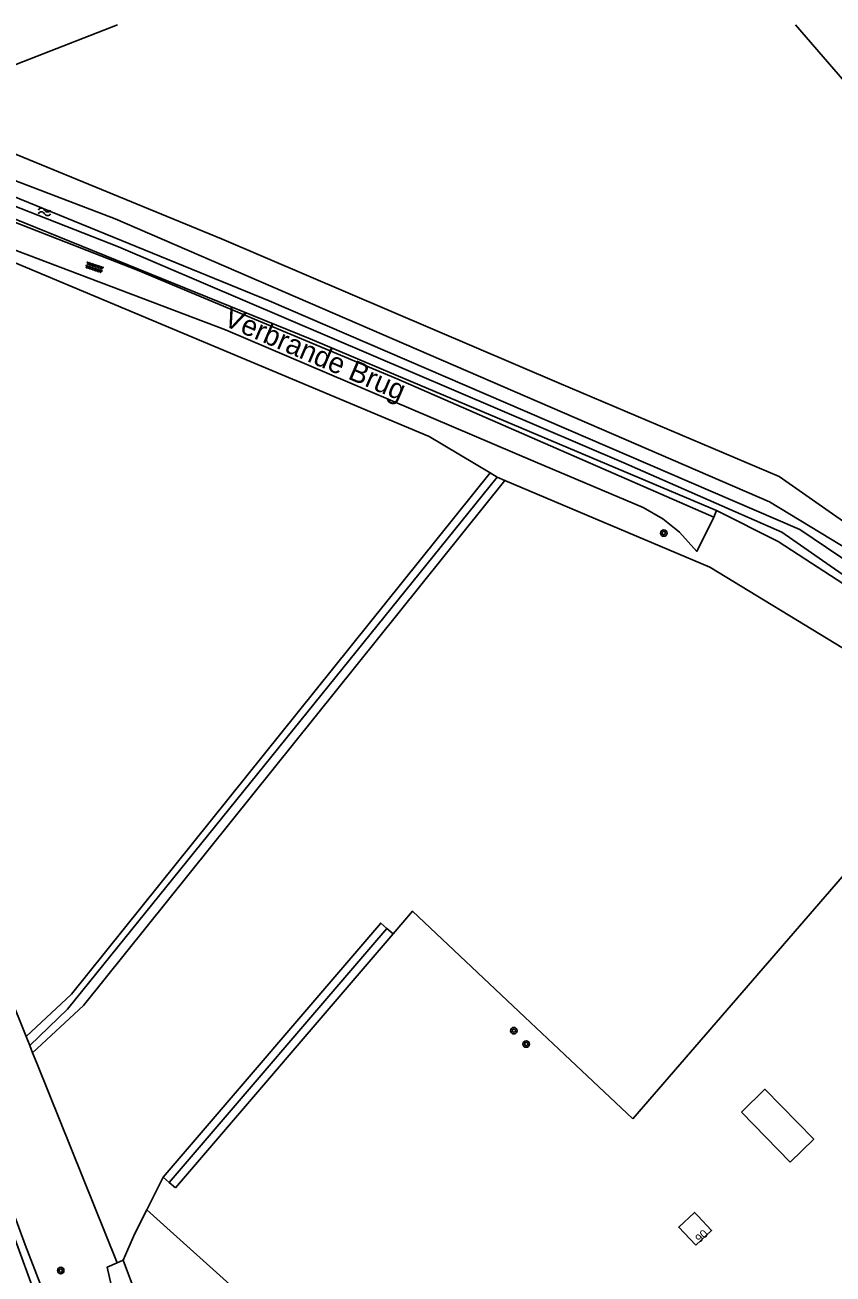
# Model space of a CAD drawing. Extents: x 135990 to 139000, y 393500 to 396000.
# Drawn here: x 136176.4 to 136274.9, y 395847.7 to 396000 of the extents above; entities that cross this region are included whole.
import ezdxf

# ---------------------------------------------------------------- set-up
doc = ezdxf.new("R2010")
doc.units = 0
for name, color, linetype in [('gg-anno-huisnummerreeks BGT', 7, 'Continuous'), ('gg-anno-openbare ruimte label', 7, 'Continuous'), ('gg-bbg-gedigitaliseerde bijgebouw', 7, 'Continuous'), ('gg-bbg-hoofdgebouw', 7, 'Continuous'), ('gg-knt-bovenkant onderkant talud', 7, 'Continuous'), ('gg-knt-bronhoudergrens', 7, 'Continuous'), ('gg-knt-onverhard', 7, 'Continuous'), ('gg-knt-verharding', 7, 'Continuous'), ('gg-kntw-bovenkant insteek waterloop', 7, 'Continuous'), ('gg-kntw-midden sloot', 7, 'Continuous'), ('gg-kntw-waterlijn', 7, 'Continuous'), ('gt-grn-groengrens', 7, 'Continuous'), ('gt-symb-boom', 7, 'Continuous'), ('gt-symb-overige verharding', 7, 'Continuous'), ('gt-symb-watersymbool', 7, 'Continuous')]:
    doc.layers.add(name, color=color, linetype=linetype)

# ---------------------------------------------------------------- blocks, each defined once
blk = doc.blocks.new('gt0-BOOM')
at = {"layer": 'gt-symb-boom'}
for radius in [0.4, 0.2]:
    blk.add_circle((0, 0), radius, dxfattribs=at)
blk = doc.blocks.new('gt0-WA')
at = {"layer": 'gt-symb-watersymbool'}
for centre, start, end in [((-0.32, 0.02), 28.0725, 151.9275), ((0.43, 0.42), 208.0725, 331.9275), ((-0.32, -0.43), 28.0725, 151.9275), ((0.43, -0.03), 208.0725, 331.9275)]:
    blk.add_arc(centre, 0.425, start, end, dxfattribs=at)
blk = doc.blocks.new('gt0-OVH')
at = {"layer": 'gt-symb-overige verharding'}
for points in [[(-0.97, 0.3), (-0.97, 0.31), (-0.96, 0.32), (-0.97, 0.33), (-0.97, 0.34), (-0.98, 0.35), (-0.99, 0.35), (-1, 0.36), (-1.01, 0.35), (-1.02, 0.35), (-1.03, 0.34), (-1.03, 0.33), (-1.04, 0.32), (-1.03, 0.31), (-1.03, 0.3), (-1.02, 0.29), (-1.01, 0.29), (-1, 0.28), (-0.99, 0.29), (-0.98, 0.29)], [(-0.87, 0.11), (-0.87, 0.12), (-0.86, 0.13), (-0.87, 0.14), (-0.87, 0.15), (-0.88, 0.16), (-0.89, 0.16), (-0.9, 0.16), (-0.91, 0.16), (-0.92, 0.16), (-0.93, 0.15), (-0.93, 0.14), (-0.94, 0.13), (-0.93, 0.12), (-0.93, 0.11), (-0.92, 0.1), (-0.91, 0.09), (-0.9, 0.09), (-0.89, 0.09), (-0.88, 0.1)], [(-0.77, 0.3), (-0.77, 0.31), (-0.76, 0.32), (-0.77, 0.33), (-0.77, 0.34), (-0.78, 0.35), (-0.79, 0.35), (-0.8, 0.36), (-0.81, 0.35), (-0.82, 0.35), (-0.83, 0.34), (-0.83, 0.33), (-0.84, 0.32), (-0.83, 0.31), (-0.83, 0.3), (-0.82, 0.29), (-0.81, 0.29), (-0.8, 0.28), (-0.79, 0.29), (-0.78, 0.29)], [(-0.67, 0.11), (-0.67, 0.12), (-0.66, 0.13), (-0.67, 0.14), (-0.67, 0.15), (-0.68, 0.16), (-0.69, 0.16), (-0.7, 0.16), (-0.71, 0.16), (-0.72, 0.16), (-0.73, 0.15), (-0.73, 0.14), (-0.74, 0.13), (-0.73, 0.12), (-0.73, 0.11), (-0.72, 0.1), (-0.71, 0.09), (-0.7, 0.09), (-0.69, 0.09), (-0.68, 0.1)], [(-0.57, 0.3), (-0.57, 0.31), (-0.56, 0.32), (-0.57, 0.33), (-0.57, 0.34), (-0.58, 0.35), (-0.59, 0.35), (-0.6, 0.36), (-0.61, 0.35), (-0.62, 0.35), (-0.63, 0.34), (-0.63, 0.33), (-0.64, 0.32), (-0.63, 0.31), (-0.63, 0.3), (-0.62, 0.29), (-0.61, 0.29), (-0.6, 0.28), (-0.59, 0.29), (-0.58, 0.29)], [(-0.47, 0.11), (-0.47, 0.12), (-0.46, 0.13), (-0.47, 0.14), (-0.47, 0.15), (-0.48, 0.16), (-0.49, 0.16), (-0.5, 0.16), (-0.51, 0.16), (-0.52, 0.16), (-0.53, 0.15), (-0.53, 0.14), (-0.54, 0.13), (-0.53, 0.12), (-0.53, 0.11), (-0.52, 0.1), (-0.51, 0.09), (-0.5, 0.09), (-0.49, 0.09), (-0.48, 0.1)], [(-0.37, 0.3), (-0.37, 0.31), (-0.36, 0.32), (-0.37, 0.33), (-0.37, 0.34), (-0.38, 0.35), (-0.39, 0.35), (-0.4, 0.36), (-0.41, 0.35), (-0.42, 0.35), (-0.43, 0.34), (-0.43, 0.33), (-0.44, 0.32), (-0.43, 0.31), (-0.43, 0.3), (-0.42, 0.29), (-0.41, 0.29), (-0.4, 0.28), (-0.39, 0.29), (-0.38, 0.29)], [(-0.27, 0.11), (-0.27, 0.12), (-0.26, 0.13), (-0.27, 0.14), (-0.27, 0.15), (-0.28, 0.16), (-0.29, 0.16), (-0.3, 0.16), (-0.31, 0.16), (-0.32, 0.16), (-0.33, 0.15), (-0.33, 0.14), (-0.34, 0.13), (-0.33, 0.12), (-0.33, 0.11), (-0.32, 0.1), (-0.31, 0.09), (-0.3, 0.09), (-0.29, 0.09), (-0.28, 0.1)], [(-0.17, 0.3), (-0.17, 0.31), (-0.16, 0.32), (-0.17, 0.33), (-0.17, 0.34), (-0.18, 0.35), (-0.19, 0.35), (-0.2, 0.36), (-0.21, 0.35), (-0.22, 0.35), (-0.23, 0.34), (-0.23, 0.33), (-0.24, 0.32), (-0.23, 0.31), (-0.23, 0.3), (-0.22, 0.29), (-0.21, 0.29), (-0.2, 0.28), (-0.19, 0.29), (-0.18, 0.29)], [(-0.07, 0.11), (-0.07, 0.12), (-0.06, 0.13), (-0.07, 0.14), (-0.07, 0.15), (-0.08, 0.16), (-0.09, 0.16), (-0.1, 0.16), (-0.11, 0.16), (-0.12, 0.16), (-0.13, 0.15), (-0.13, 0.14), (-0.14, 0.13), (-0.13, 0.12), (-0.13, 0.11), (-0.12, 0.1), (-0.11, 0.09), (-0.1, 0.09), (-0.09, 0.09), (-0.08, 0.1)], [(0.03, 0.3), (0.03, 0.31), (0.04, 0.32), (0.03, 0.33), (0.03, 0.34), (0.02, 0.35), (0.01, 0.35), (0, 0.36), (-0.01, 0.35), (-0.02, 0.35), (-0.03, 0.34), (-0.03, 0.33), (-0.04, 0.32), (-0.03, 0.31), (-0.03, 0.3), (-0.02, 0.29), (-0.01, 0.29), (0, 0.28), (0.01, 0.29), (0.02, 0.29)], [(0.13, 0.11), (0.13, 0.12), (0.14, 0.13), (0.13, 0.14), (0.13, 0.15), (0.12, 0.16), (0.11, 0.16), (0.1, 0.16), (0.09, 0.16), (0.08, 0.16), (0.07, 0.15), (0.07, 0.14), (0.06, 0.13), (0.07, 0.12), (0.07, 0.11), (0.08, 0.1), (0.09, 0.09), (0.1, 0.09), (0.11, 0.09), (0.12, 0.1)], [(0.23, 0.3), (0.23, 0.31), (0.24, 0.32), (0.23, 0.33), (0.23, 0.34), (0.22, 0.35), (0.21, 0.35), (0.2, 0.36), (0.19, 0.35), (0.18, 0.35), (0.17, 0.34), (0.17, 0.33), (0.16, 0.32), (0.17, 0.31), (0.17, 0.3), (0.18, 0.29), (0.19, 0.29), (0.2, 0.28), (0.21, 0.29), (0.22, 0.29)], [(0.33, 0.11), (0.33, 0.12), (0.34, 0.13), (0.33, 0.14), (0.33, 0.15), (0.32, 0.16), (0.31, 0.16), (0.3, 0.16), (0.29, 0.16), (0.28, 0.16), (0.27, 0.15), (0.27, 0.14), (0.26, 0.13), (0.27, 0.12), (0.27, 0.11), (0.28, 0.1), (0.29, 0.09), (0.3, 0.09), (0.31, 0.09), (0.32, 0.1)], [(0.43, 0.3), (0.43, 0.31), (0.44, 0.32), (0.43, 0.33), (0.43, 0.34), (0.42, 0.35), (0.41, 0.35), (0.4, 0.36), (0.39, 0.35), (0.38, 0.35), (0.37, 0.34), (0.37, 0.33), (0.36, 0.32), (0.37, 0.31), (0.37, 0.3), (0.38, 0.29), (0.39, 0.29), (0.4, 0.28), (0.41, 0.29), (0.42, 0.29)], [(0.53, 0.11), (0.53, 0.12), (0.54, 0.13), (0.53, 0.14), (0.53, 0.15), (0.52, 0.16), (0.51, 0.16), (0.5, 0.16), (0.49, 0.16), (0.48, 0.16), (0.47, 0.15), (0.47, 0.14), (0.46, 0.13), (0.47, 0.12), (0.47, 0.11), (0.48, 0.1), (0.49, 0.09), (0.5, 0.09), (0.51, 0.09), (0.52, 0.1)], [(0.63, 0.3), (0.63, 0.31), (0.64, 0.32), (0.63, 0.33), (0.63, 0.34), (0.62, 0.35), (0.61, 0.35), (0.6, 0.36), (0.59, 0.35), (0.58, 0.35), (0.57, 0.34), (0.57, 0.33), (0.56, 0.32), (0.57, 0.31), (0.57, 0.3), (0.58, 0.29), (0.59, 0.29), (0.6, 0.28), (0.61, 0.29), (0.62, 0.29)], [(0.73, 0.11), (0.73, 0.12), (0.74, 0.13), (0.73, 0.14), (0.73, 0.15), (0.72, 0.16), (0.71, 0.16), (0.7, 0.16), (0.69, 0.16), (0.68, 0.16), (0.67, 0.15), (0.67, 0.14), (0.66, 0.13), (0.67, 0.12), (0.67, 0.11), (0.68, 0.1), (0.69, 0.09), (0.7, 0.09), (0.71, 0.09), (0.72, 0.1)], [(0.83, 0.3), (0.83, 0.31), (0.84, 0.32), (0.83, 0.33), (0.83, 0.34), (0.82, 0.35), (0.81, 0.35), (0.8, 0.36), (0.79, 0.35), (0.78, 0.35), (0.77, 0.34), (0.77, 0.33), (0.76, 0.32), (0.77, 0.31), (0.77, 0.3), (0.78, 0.29), (0.79, 0.29), (0.8, 0.28), (0.81, 0.29), (0.82, 0.29)], [(0.93, 0.11), (0.93, 0.12), (0.94, 0.13), (0.93, 0.14), (0.93, 0.15), (0.92, 0.16), (0.91, 0.16), (0.9, 0.16), (0.89, 0.16), (0.88, 0.16), (0.87, 0.15), (0.87, 0.14), (0.86, 0.13), (0.87, 0.12), (0.87, 0.11), (0.88, 0.1), (0.89, 0.09), (0.9, 0.09), (0.91, 0.09), (0.92, 0.1)], [(1.03, 0.3), (1.03, 0.31), (1.04, 0.32), (1.03, 0.33), (1.03, 0.34), (1.02, 0.35), (1.01, 0.35), (1, 0.36), (0.99, 0.35), (0.98, 0.35), (0.97, 0.34), (0.97, 0.33), (0.96, 0.32), (0.97, 0.31), (0.97, 0.3), (0.98, 0.29), (0.99, 0.29), (1, 0.28), (1.01, 0.29), (1.02, 0.29)], [(-0.97, -0.14), (-0.97, -0.13), (-0.96, -0.12), (-0.97, -0.11), (-0.97, -0.1), (-0.98, -0.09), (-0.99, -0.09), (-1, -0.08), (-1.01, -0.09), (-1.02, -0.09), (-1.03, -0.1), (-1.03, -0.11), (-1.04, -0.12), (-1.03, -0.13), (-1.03, -0.14), (-1.02, -0.15), (-1.01, -0.15), (-1, -0.16), (-0.99, -0.15), (-0.98, -0.15)], [(-0.87, -0.33), (-0.87, -0.32), (-0.86, -0.31), (-0.87, -0.3), (-0.87, -0.29), (-0.88, -0.28), (-0.89, -0.28), (-0.9, -0.28), (-0.91, -0.28), (-0.92, -0.28), (-0.93, -0.29), (-0.93, -0.3), (-0.94, -0.31), (-0.93, -0.32), (-0.93, -0.33), (-0.92, -0.34), (-0.91, -0.35), (-0.9, -0.35), (-0.89, -0.35), (-0.88, -0.34)], [(-0.77, -0.14), (-0.77, -0.13), (-0.76, -0.12), (-0.77, -0.11), (-0.77, -0.1), (-0.78, -0.09), (-0.79, -0.09), (-0.8, -0.08), (-0.81, -0.09), (-0.82, -0.09), (-0.83, -0.1), (-0.83, -0.11), (-0.84, -0.12), (-0.83, -0.13), (-0.83, -0.14), (-0.82, -0.15), (-0.81, -0.15), (-0.8, -0.16), (-0.79, -0.15), (-0.78, -0.15)], [(-0.67, -0.33), (-0.67, -0.32), (-0.66, -0.31), (-0.67, -0.3), (-0.67, -0.29), (-0.68, -0.28), (-0.69, -0.28), (-0.7, -0.28), (-0.71, -0.28), (-0.72, -0.28), (-0.73, -0.29), (-0.73, -0.3), (-0.74, -0.31), (-0.73, -0.32), (-0.73, -0.33), (-0.72, -0.34), (-0.71, -0.35), (-0.7, -0.35), (-0.69, -0.35), (-0.68, -0.34)], [(-0.57, -0.14), (-0.57, -0.13), (-0.56, -0.12), (-0.57, -0.11), (-0.57, -0.1), (-0.58, -0.09), (-0.59, -0.09), (-0.6, -0.08), (-0.61, -0.09), (-0.62, -0.09), (-0.63, -0.1), (-0.63, -0.11), (-0.64, -0.12), (-0.63, -0.13), (-0.63, -0.14), (-0.62, -0.15), (-0.61, -0.15), (-0.6, -0.16), (-0.59, -0.15), (-0.58, -0.15)], [(-0.47, -0.33), (-0.47, -0.32), (-0.46, -0.31), (-0.47, -0.3), (-0.47, -0.29), (-0.48, -0.28), (-0.49, -0.28), (-0.5, -0.28), (-0.51, -0.28), (-0.52, -0.28), (-0.53, -0.29), (-0.53, -0.3), (-0.54, -0.31), (-0.53, -0.32), (-0.53, -0.33), (-0.52, -0.34), (-0.51, -0.35), (-0.5, -0.35), (-0.49, -0.35), (-0.48, -0.34)], [(-0.37, -0.14), (-0.37, -0.13), (-0.36, -0.12), (-0.37, -0.11), (-0.37, -0.1), (-0.38, -0.09), (-0.39, -0.09), (-0.4, -0.08), (-0.41, -0.09), (-0.42, -0.09), (-0.43, -0.1), (-0.43, -0.11), (-0.44, -0.12), (-0.43, -0.13), (-0.43, -0.14), (-0.42, -0.15), (-0.41, -0.15), (-0.4, -0.16), (-0.39, -0.15), (-0.38, -0.15)], [(-0.27, -0.33), (-0.27, -0.32), (-0.26, -0.31), (-0.27, -0.3), (-0.27, -0.29), (-0.28, -0.28), (-0.29, -0.28), (-0.3, -0.28), (-0.31, -0.28), (-0.32, -0.28), (-0.33, -0.29), (-0.33, -0.3), (-0.34, -0.31), (-0.33, -0.32), (-0.33, -0.33), (-0.32, -0.34), (-0.31, -0.35), (-0.3, -0.35), (-0.29, -0.35), (-0.28, -0.34)], [(-0.17, -0.14), (-0.17, -0.13), (-0.16, -0.12), (-0.17, -0.11), (-0.17, -0.1), (-0.18, -0.09), (-0.19, -0.09), (-0.2, -0.08), (-0.21, -0.09), (-0.22, -0.09), (-0.23, -0.1), (-0.23, -0.11), (-0.24, -0.12), (-0.23, -0.13), (-0.23, -0.14), (-0.22, -0.15), (-0.21, -0.15), (-0.2, -0.16), (-0.19, -0.15), (-0.18, -0.15)], [(-0.07, -0.33), (-0.07, -0.32), (-0.06, -0.31), (-0.07, -0.3), (-0.07, -0.29), (-0.08, -0.28), (-0.09, -0.28), (-0.1, -0.28), (-0.11, -0.28), (-0.12, -0.28), (-0.13, -0.29), (-0.13, -0.3), (-0.14, -0.31), (-0.13, -0.32), (-0.13, -0.33), (-0.12, -0.34), (-0.11, -0.35), (-0.1, -0.35), (-0.09, -0.35), (-0.08, -0.34)], [(0.03, -0.14), (0.03, -0.13), (0.04, -0.12), (0.03, -0.11), (0.03, -0.1), (0.02, -0.09), (0.01, -0.09), (0, -0.08), (-0.01, -0.09), (-0.02, -0.09), (-0.03, -0.1), (-0.03, -0.11), (-0.04, -0.12), (-0.03, -0.13), (-0.03, -0.14), (-0.02, -0.15), (-0.01, -0.15), (0, -0.16), (0.01, -0.15), (0.02, -0.15)], [(0.13, -0.33), (0.13, -0.32), (0.14, -0.31), (0.13, -0.3), (0.13, -0.29), (0.12, -0.28), (0.11, -0.28), (0.1, -0.28), (0.09, -0.28), (0.08, -0.28), (0.07, -0.29), (0.07, -0.3), (0.06, -0.31), (0.07, -0.32), (0.07, -0.33), (0.08, -0.34), (0.09, -0.35), (0.1, -0.35), (0.11, -0.35), (0.12, -0.34)], [(0.23, -0.14), (0.23, -0.13), (0.24, -0.12), (0.23, -0.11), (0.23, -0.1), (0.22, -0.09), (0.21, -0.09), (0.2, -0.08), (0.19, -0.09), (0.18, -0.09), (0.17, -0.1), (0.17, -0.11), (0.16, -0.12), (0.17, -0.13), (0.17, -0.14), (0.18, -0.15), (0.19, -0.15), (0.2, -0.16), (0.21, -0.15), (0.22, -0.15)], [(0.33, -0.33), (0.33, -0.32), (0.34, -0.31), (0.33, -0.3), (0.33, -0.29), (0.32, -0.28), (0.31, -0.28), (0.3, -0.28), (0.29, -0.28), (0.28, -0.28), (0.27, -0.29), (0.27, -0.3), (0.26, -0.31), (0.27, -0.32), (0.27, -0.33), (0.28, -0.34), (0.29, -0.35), (0.3, -0.35), (0.31, -0.35), (0.32, -0.34)], [(0.43, -0.14), (0.43, -0.13), (0.44, -0.12), (0.43, -0.11), (0.43, -0.1), (0.42, -0.09), (0.41, -0.09), (0.4, -0.08), (0.39, -0.09), (0.38, -0.09), (0.37, -0.1), (0.37, -0.11), (0.36, -0.12), (0.37, -0.13), (0.37, -0.14), (0.38, -0.15), (0.39, -0.15), (0.4, -0.16), (0.41, -0.15), (0.42, -0.15)], [(0.53, -0.33), (0.53, -0.32), (0.54, -0.31), (0.53, -0.3), (0.53, -0.29), (0.52, -0.28), (0.51, -0.28), (0.5, -0.28), (0.49, -0.28), (0.48, -0.28), (0.47, -0.29), (0.47, -0.3), (0.46, -0.31), (0.47, -0.32), (0.47, -0.33), (0.48, -0.34), (0.49, -0.35), (0.5, -0.35), (0.51, -0.35), (0.52, -0.34)], [(0.63, -0.14), (0.63, -0.13), (0.64, -0.12), (0.63, -0.11), (0.63, -0.1), (0.62, -0.09), (0.61, -0.09), (0.6, -0.08), (0.59, -0.09), (0.58, -0.09), (0.57, -0.1), (0.57, -0.11), (0.56, -0.12), (0.57, -0.13), (0.57, -0.14), (0.58, -0.15), (0.59, -0.15), (0.6, -0.16), (0.61, -0.15), (0.62, -0.15)], [(0.73, -0.33), (0.73, -0.32), (0.74, -0.31), (0.73, -0.3), (0.73, -0.29), (0.72, -0.28), (0.71, -0.28), (0.7, -0.28), (0.69, -0.28), (0.68, -0.28), (0.67, -0.29), (0.67, -0.3), (0.66, -0.31), (0.67, -0.32), (0.67, -0.33), (0.68, -0.34), (0.69, -0.35), (0.7, -0.35), (0.71, -0.35), (0.72, -0.34)], [(0.83, -0.14), (0.83, -0.13), (0.84, -0.12), (0.83, -0.11), (0.83, -0.1), (0.82, -0.09), (0.81, -0.09), (0.8, -0.08), (0.79, -0.09), (0.78, -0.09), (0.77, -0.1), (0.77, -0.11), (0.76, -0.12), (0.77, -0.13), (0.77, -0.14), (0.78, -0.15), (0.79, -0.15), (0.8, -0.16), (0.81, -0.15), (0.82, -0.15)], [(0.93, -0.33), (0.93, -0.32), (0.94, -0.31), (0.93, -0.3), (0.93, -0.29), (0.92, -0.28), (0.91, -0.28), (0.9, -0.28), (0.89, -0.28), (0.88, -0.28), (0.87, -0.29), (0.87, -0.3), (0.86, -0.31), (0.87, -0.32), (0.87, -0.33), (0.88, -0.34), (0.89, -0.35), (0.9, -0.35), (0.91, -0.35), (0.92, -0.34)], [(1.03, -0.14), (1.03, -0.13), (1.04, -0.12), (1.03, -0.11), (1.03, -0.1), (1.02, -0.09), (1.01, -0.09), (1, -0.08), (0.99, -0.09), (0.98, -0.09), (0.97, -0.1), (0.97, -0.11), (0.96, -0.12), (0.97, -0.13), (0.97, -0.14), (0.98, -0.15), (0.99, -0.15), (1, -0.16), (1.01, -0.15), (1.02, -0.15)]]:
    blk.add_lwpolyline(points, close=True, dxfattribs=at)

msp = doc.modelspace()

# ---------------------------------------------------------------- linework, layer by layer
at = {"layer": 'gg-bbg-gedigitaliseerde bijgebouw'}
msp.add_lwpolyline([(136263.755, 395867.413), (136266.614, 395870.211), (136272.559, 395864.136), (136269.7, 395861.338), (136263.755, 395867.413)], dxfattribs=at)
at = {"layer": 'gg-bbg-hoofdgebouw'}
msp.add_line((136256.754, 395852.722), (136258.19, 395851.19), dxfattribs=at)
for points in [[(136258.435, 395854.788), (136258.04, 395855.21), (136256.11, 395853.41), (136256.754, 395852.722)], [(136258.19, 395851.19), (136260.12, 395852.99), (136258.435, 395854.788)]]:
    msp.add_lwpolyline(points, dxfattribs=at)
at = {"layer": 'gg-knt-bovenkant onderkant talud'}
msp.add_lwpolyline([(136201.244, 395796.154), (136195.273, 395801.183), (136192.468, 395809.72), (136176.417, 395851.255), (136158.526, 395900.168), (136141.395, 395948.185), (136130.007, 395978.958)], dxfattribs=at)
at = {"layer": 'gg-knt-bronhoudergrens'}
msp.add_line((136191.248, 395855.527), (136223.025, 395826.98), dxfattribs=at)
msp.add_lwpolyline([(136188.363, 395849.377), (136189.793, 395852.617), (136191.248, 395855.527)], dxfattribs=at)
at = {"layer": 'gg-knt-onverhard'}
for points in [[(136260.368, 395939.987), (136258.308, 395935.803), (136256.192, 395938.164), (136254.175, 395939.769), (136251.756, 395941.172), (136238.608, 395946.725), (136200.866, 395962.833), (136156.336, 395979.68), (136140.928, 395985.882)], [(136151.405, 395985.232), (136190.126, 395970.103), (136221.87, 395956.798), (136260.368, 395939.987)]]:
    msp.add_lwpolyline(points, dxfattribs=at)
at = {"layer": 'gg-knt-verharding'}
msp.add_lwpolyline([(136194.84, 395798.55), (136194.304, 395799.262), (136191.281, 395807.835), (136175.523, 395851.013), (136140.515, 395947.835), (136125.623, 395988.445)], dxfattribs=at)
at = {"layer": 'gg-kntw-bovenkant insteek waterloop'}
msp.add_line((136187.663, 395849.065), (136188.363, 395849.377), dxfattribs=at)
for points in [[(136151.86, 395992.871), (136150.244, 395991.832), (136150.736, 395991.101), (136152.541, 395989.289), (136160.654, 395986.547), (136187.413, 395976.377), (136267.176, 395941.857), (136279.571, 395934.316), (136290.57, 395925.713), (136327.125, 395886.537)], [(136260.701, 395940.796), (136211.178, 395961.745), (136147.051, 395987.75), (136146.665, 395988.937)], [(136294.641, 395916.542), (136288.506, 395923.2), (136277.06, 395931.3), (136268.239, 395936.998), (136260.701, 395940.796)], [(136188.363, 395849.377), (136189.262, 395846.982), (136200.173, 395819.057), (136201.434, 395812.944)], [(136219.003, 395796.356), (136199.198, 395810.289), (136197.929, 395818.163), (136186.924, 395846.364), (136186.411, 395848.506), (136187.663, 395849.065)]]:
    msp.add_lwpolyline(points, dxfattribs=at)
at = {"layer": 'gg-kntw-midden sloot'}
for p, q in [((136220.534, 395889.837), (136194.006, 395858.835)), ((136176.982, 395875.558), (136176.537, 395876.661)), ((136177.338, 395874.675), (136176.982, 395875.558)), ((136177.849, 395873.408), (136177.338, 395874.675)), ((136187.663, 395849.065), (136177.849, 395873.408))]:
    msp.add_line(p, q, dxfattribs=at)
for points in [[(136137.299, 395977.743), (136139.863, 395978.077), (136175.196, 395970.996), (136225.687, 395949.807)], [(136176.537, 395876.661), (136170.293, 395892.151), (136149.783, 395946.573), (136137.299, 395977.743)], [(136233.969, 395944.874), (136181.613, 395879.974), (136176.982, 395875.558)]]:
    msp.add_lwpolyline(points, dxfattribs=at)
at = {"layer": 'gg-kntw-waterlijn'}
for points in [[(136164.548, 396000), (136149.157, 395993.938), (136147.368, 395992.701), (136147.921, 395989.122), (136149.771, 395987.857), (136187.797, 395972.933), (136249.43, 395946.591), (136268.682, 395938.154), (136274.582, 395934.054), (136288.114, 395924.649)], [(136279.098, 395932.901), (136270.859, 395938.459), (136260.015, 395943.136), (136230.027, 395956.07), (136206.184, 395966.352), (136174.835, 395979.164), (136152.487, 395987.78), (136150.787, 395988.875), (136149.064, 395990.487), (136148.872, 395992.283), (136149.276, 395992.676), (136159.047, 395996.687), (136167.434, 396000)]]:
    msp.add_lwpolyline(points, dxfattribs=at)
at = {"layer": 'gt-grn-groengrens'}
for p, q in [((136270.332, 396000), (136304.542, 395960.422)), ((136225.687, 395949.807), (136233.101, 395945.391)), ((136233.101, 395945.391), (136233.969, 395944.874)), ((136233.969, 395944.874), (136234.926, 395944.469)), ((136260.701, 395940.796), (136260.368, 395939.987)), ((136289.783, 395912.065), (136250.503, 395866.604)), ((136194.766, 395858.185), (136221.294, 395889.187)), ((136221.294, 395889.187), (136220.534, 395889.837)), ((136193.246, 395859.485), (136191.248, 395855.527)), ((136193.246, 395859.485), (136194.006, 395858.835)), ((136194.006, 395858.835), (136194.766, 395858.185))]:
    msp.add_line(p, q, dxfattribs=at)
for points in [[(136187.706, 396000), (136163.811, 395990.712), (136162.186, 395989.628), (136200.373, 395973.92), (136241.539, 395956.317), (136268.351, 395944.942), (136282.705, 395934.921), (136298.142, 395923.546), (136313.308, 395906.755), (136329.847, 395889.355)], [(136233.101, 395945.391), (136182.079, 395881.806), (136176.537, 395876.661)], [(136177.338, 395874.675), (136183.547, 395880.44), (136234.926, 395944.469)], [(136234.926, 395944.469), (136259.914, 395933.886), (136276.21, 395923.984), (136289.783, 395912.065)], [(136237.343, 395879.001), (136223.631, 395891.918), (136221.294, 395889.187)], [(136220.534, 395889.837), (136219.774, 395890.487), (136193.246, 395859.485)], [(136250.503, 395866.604), (136242.18, 395874.445), (136237.343, 395879.001)]]:
    msp.add_lwpolyline(points, dxfattribs=at)

# ---------------------------------------------------------------- block references
at = {"layer": 'gt-symb-boom'}
for p in [(136254.285, 395938.045), (136236.01, 395877.364), (136237.52, 395875.734), (136180.766, 395848.109)]:
    msp.add_blockref('gt0-BOOM', p, dxfattribs=at)
at = {"layer": 'gt-symb-overige verharding', "rotation": -18.416834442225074}
msp.add_blockref('gt0-OVH', (136184.868, 395970.438), dxfattribs=at)
at = {"layer": 'gt-symb-watersymbool'}
msp.add_blockref('gt0-WA', (136178.734, 395977.218), dxfattribs=at)

# ---------------------------------------------------------------- texts
at = {"layer": 'gg-anno-huisnummerreeks BGT'}
msp.add_text('90', height=1, rotation=43, dxfattribs=at).set_placement((136258.679, 395851.46))
at = {"layer": 'gg-anno-openbare ruimte label'}
msp.add_text('Verbrande Brug', height=2.5, rotation=336.8, dxfattribs=at).set_placement((136200.457, 395963.424))

doc.saveas('drawing.dxf')
